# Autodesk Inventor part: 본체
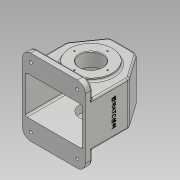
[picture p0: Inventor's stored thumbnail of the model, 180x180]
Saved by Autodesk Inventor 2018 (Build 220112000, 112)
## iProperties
Created: 2022-12
Part Number: 본체
Material: 알루미늄 6061
Document SubType Name: Modeling
Designer: home
Density: 2.7 g/cm^3
Appearance: 알루미늄 - 평지
Mass: 937.22 g
Surface Area: 1065.22 cm^2
Volume: 347.118 cm^3
Author: home
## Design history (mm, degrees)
sketch "스케치1"
  geometry: L1 (-55, -38.5)-(55, -38.5); L2 (55, -38.5)-(55, 38.5); L3 (55, 38.5)-(-55, 38.5); L4 (-55, 38.5)-(-55, -38.5); L5 (-55, -38.5)-(55, 38.5); L6 (55, -38.5)-(-55, 38.5); L7 (-55, 38.5)-(-23.491, 83.5); L8 (-23.491, 83.5)-(23.491, 83.5); L9 (23.491, 83.5)-(55, 38.5); 1 further point
  constraints: 18 end point, 2 horizontal, 2 midpoint, 2 parallel, 1 equal length, 1 perpendicular
  dimensions: "d0" = 110 distance of L3.end L2.end; "d1" = 77 distance of L2.end L1.end; "d2" = 122 distance between parallel lines of L1 L8; "d3" = 35 deg angle of L4 L7
extrude "돌출1" new body sketch "스케치1" distance "d4" = 77; taper "d5" = 0 deg
fillet "모깎기1" dims "d6" = 10
fillet "모깎기2" dims "d7" = 3
feature "쉘1" dims "d8" = 5
sketch "스케치2"
  geometry: L1 (2, 72)-(102, 72) reference; L2 (0, 0)-(104, 0) reference; L3 (107, 3)-(107, 74) reference; L4 (0, 77)-(104, 77) reference; L5 (-3, 3)-(-3, 74) reference; L6 (102, 5)-(102, 72) reference; L7 (102, 72)-(2, 72) reference; L8 (2, 72)-(2, 5) reference; L9 (2, 5)-(102, 5) reference; L10 (0, 77)-(104, 77) reference; L11 (107, 74)-(107, 3) reference; L12 (104, 0)-(0, 0) reference; L13 (-3, 3)-(-3, 74) reference; L14 (33.715, 77)-(70.285, 77) reference; L15 (52, 77)-(52, 0); L16 (11, 105.5)-(93, 105.5); L17 (107, 91.5)-(107, -14.5); L18 (93, -28.5)-(11, -28.5); L19 (-3, -14.5)-(-3, 91.5); L20 (-3, 105.5)-(107, -28.5); L21 (107, 105.5)-(-3, -28.5); A1 r 3 centre (0, 3) between (-3, 3) and (0, 0) reference; A2 r 3 centre (104, 3) between (104, 0) and (107, 3) reference; A3 r 3 centre (104, 74) between (107, 74) and (104, 77) reference; A4 r 3 centre (0, 74) between (0, 77) and (-3, 74) reference; A5 r 3 centre (0, 74) between (0, 77) and (-3, 74) reference; A6 r 3 centre (104, 74) between (107, 74) and (104, 77) reference; A7 r 3 centre (104, 3) between (104, 0) and (107, 3) reference; A8 r 3 centre (0, 3) between (-3, 3) and (0, 0) reference; A9 r 14 centre (93, 91.5) between (107, 91.5) and (93, 105.5); A10 r 14 centre (93, -14.5) between (93, -28.5) and (107, -14.5); A11 r 14 centre (11, -14.5) between (-3, -14.5) and (11, -28.5); A12 r 14 centre (11, 91.5) between (11, 105.5) and (-3, 91.5); 1 further point
  constraints: 14 end point, 8 point on circle, 8 point on line, 8 tangent, 4 centre point, 4 midpoint, 3 equal radius, 2 parallel, 2 perpendicular, 1 horizontal
  dimensions: "d9" = 134 distance of L21.start L20.end; "d10" = 110 distance of L20.end L21.end; "d11" = 14 radius of A9
extrude "돌출2" join sketch "스케치2" distance "d12" = 12; taper "d13" = 0 deg
node "작업 평면1"
sketch "스케치5"
  geometry: L1 (-50, -38.5)-(50, -38.5) reference; L2 (0, -38.5)-(0, 26.5); C1 r 20 at (0, 26.5); 1 further point
  constraints: 2 end point, 1 centre point, 1 coincident, 1 midpoint, 1 vertical
  dimensions: "d14" = 65 distance of L2.start L2.end; "d15" = 40 diameter of C1
extrude "돌출3" cut sketch "스케치5" extent not by distance; stored distance "d16" = 5; taper "d17" = 0 deg
sketch "스케치6"
  geometry: L1 (2, 11.153)-(2, -28.847) reference; L2 (2, -8.847)-(69, -8.847); L3 (69, -28.847)-(69, 11.153) reference; L4 (16, -8.847)-(16, -28.847); L5 (2, 0)-(2, -73.847) reference; L6 (16, -28.847)-(-8, -28.847); L7 (-8, -28.847)-(-8, -46.347); L8 (-8, -46.347)-(-3, -46.347); L9 (-3, -61.847)-(-3, 0) reference; L10 (-3, -46.347)-(2, -46.347); L11 (2, -49.847)-(2, -46.347); L12 (-3, 4.015)-(-3, 42.168) reference; L13 (2, -49.847)-(16, -35.847); L14 (16, -35.847)-(16, -28.847); 1 further point
  constraints: 18 end point, 6 point on line, 4 perpendicular, 2 midpoint, 2 vertical, 1 horizontal
  dimensions: "d18" = 40 diameter of L6 L2; "d20" = 24 distance between parallel lines of L7 L4; "d21" = 5 distance between parallel lines of L12 L7; "d22" = 75 diameter of L8 L2; "d23" = 54 diameter of L13.end L2; "d24" = 135 deg angle of L5 L13
revolve "회전1" sketch "스케치6" stored, may be unused: angle "d25" = 90 deg
sketch "스케치7"
  geometry: C1 r 20 at (0, 26.5) reference; C2 r 31 at (0, 26.5); 1 further point
  constraints: 1 centre point, 1 coincident
  dimensions: "d26" = 62 diameter of C2
extrude "돌출4" join sketch "스케치7" distance "d27" = 10; taper "d28" = 0 deg
sketch "스케치8"
  geometry: C1 r 6 at (18.285, -35.5); 1 further point
  constraints: 1 centre point, 1 vertical alignment
  dimensions: "d29" = 12 diameter of C1; "d30" = 38.5 distance of point (18.285, 3) C1.centre
extrude "돌출5" join sketch "스케치8" distance "d31" = 4; taper "d32" = 0 deg
sketch "스케치9" dims "d33" = 58
  geometry: C1 r 37.5 at (0, 0) reference; C2 r 20 at (0, 0) reference; 3 further points
  constraints: 2 vertical alignment, 1 coincident, 2 other
hole "구멍1" sketch "스케치9" at (0, 29) diameter "d34" = 2.459; stored, may be unused: countersink angle "d38" = 82 deg, drill point angle "d40" = 118 deg; dims "d35" = 6, "d36" = 3.023, "d37" = 2, "d39" = 8
sketch "스케치10" dims "d41" = 52
  geometry: C1 r 20 at (0, 0) reference; C2 r 31 at (0, 0) reference; 3 further points
  constraints: 2 vertical alignment, 1 coincident, 2 other
hole "구멍2" sketch "스케치10" at (0, 26) diameter "d42" = 2.459; stored, may be unused: countersink angle "d46" = 82 deg, drill point angle "d48" = 118 deg; dims "d43" = 6, "d44" = 3.023, "d45" = 2, "d47" = 8
hole "구멍3" diameter "d51" = 5.188; stored, may be unused: countersink angle "d55" = 82 deg, drill point angle "d57" = 118 deg; dims "d52" = 20, "d53" = 3.023, "d54" = 2, "d56" = 16, "d58" = 10, "d59" = 10
sketch "스케치11"
  geometry: L1 (102, -72)-(102, -5) reference; L2 (102, -5)-(2, -5) reference; L3 (2, -5)-(2, -72) reference; L4 (2, -72)-(102, -72) reference; L5 (0, 0)-(104, 0) reference; L6 (107, 14.5)-(107, -3) reference; L7 (11, 28.5)-(93, 28.5) reference; L8 (-3, -3)-(-3, 14.5) reference; L9 (-3, -74)-(-3, -3) reference; L10 (104, -77)-(0, -77) reference; L11 (107, -74)-(107, -91.5) reference; L12 (93, -105.5)-(11, -105.5) reference; L13 (-3, -91.5)-(-3, -74) reference; L14 (107, -3)-(107, -74) reference; A1 r 14 centre (11, -91.5) between (-3, -91.5) and (11, -105.5) reference; A2 r 14 centre (93, -91.5) between (93, -105.5) and (107, -91.5) reference; A3 r 3 centre (0, -3) between (0, 0) and (-3, -3) reference; A4 r 3 centre (104, -3) between (107, -3) and (104, 0) reference; A5 r 14 centre (93, 14.5) between (107, 14.5) and (93, 28.5) reference; A6 r 14 centre (11, 14.5) between (11, 28.5) and (-3, 14.5) reference; A7 r 3 centre (0, -74) between (-3, -74) and (0, -77) reference; A8 r 3 centre (104, -74) between (104, -77) and (107, -74) reference; A9 r 14 centre (93, -91.5) between (93, -105.5) and (107, -91.5) reference; A10 r 14 centre (11, -91.5) between (-3, -91.5) and (11, -105.5) reference; 1 further point
hole "구멍4" sketch "스케치11" at (11, -91.5), (93, -91.5), (93, 14.5), (11, 14.5) diameter "d63" = 5.5; stored, may be unused: countersink angle "d67" = 82 deg, drill point angle "d69" = 118 deg; dims "d64" = 12, "d65" = 15, "d66" = 2, "d68" = 16
chamfer "모따기1" distance "d70" = 1; stored, may be unused: second distance "d71" = 2, angle "d72" = 45 deg
fillet "모깎기3" dims "d73" = 3
fillet "모깎기4" dims "d74" = 3
fillet "모깎기5" dims "d75" = 3
fillet "모깎기6" dims "d76" = 3
fillet "모깎기7" dims "d77" = 3
sketch "스케치12"
  geometry: L1 (88.5, -73.847)-(-17.5, -73.847) reference; L2 (-3, 0)-(-3, -58.847) reference; 2 further points
  constraints: 1 other
  dimensions: "d78" = 50 distance from line of L1 point (35.5, -23.847); "d79" = 38.5 distance from line of L2 point (35.5, -23.847)
feature "엠보싱1" sketch "스케치12" dims "d0" = 110, "d1" = 77, "d2" = 122, "d3" = 35 deg, "d80" = 0.5, "d81" = 0
node "솔리드1"
pattern_circular "원형 패턴1" dims angle "d61" = 360 deg
node "절단 모서리 투영1"
node "절단 모서리 투영3"
